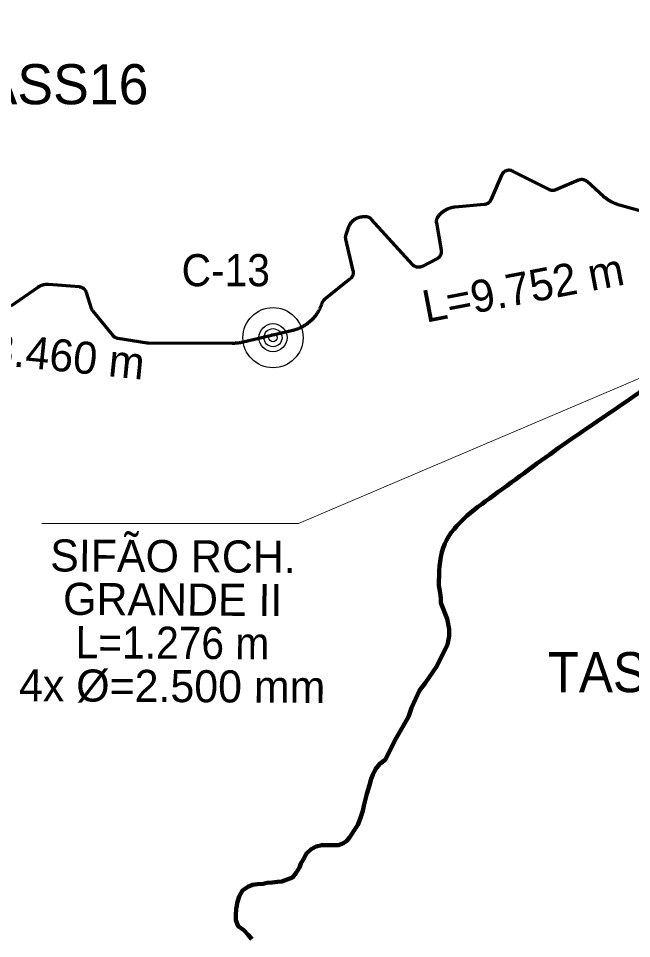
# Model space of a CAD drawing. Extents: x -1643653 to 4543381, y 1624270 to 13878484.
# Drawn here: x 659966 to 667613, y 8945036 to 8956510 of the extents above; entities that cross this region are included whole.
import ezdxf
from ezdxf.enums import TextEntityAlignment as Align

# ---------------------------------------------------------------- set-up
doc = ezdxf.new("R2010")
doc.units = 0
doc.header["$LTSCALE"] = 160
for name, color, linetype, lineweight in [('15', 7, 'Continuous', 25), ('24', 7, 'Continuous', 25), ('50', 7, 'Continuous', 13), ('53', 7, 'Continuous', 106), ('54', 7, 'Continuous', 25), ('60', 7, 'Continuous', 13), ('61', 7, 'Continuous', 70)]:
    doc.layers.add(name, color=color, linetype=linetype, lineweight=lineweight)

msp = doc.modelspace()

# ---------------------------------------------------------------- linework, layer by layer
at = {"layer": '15'}
for radius in [375, 175, 112.5, 50]:
    msp.add_circle((663140.8, 8952529.1), radius, dxfattribs=at)
at = {"layer": '24'}
for points in [[(664829.8, 8947803.3), (664867.6, 8947912.5), (664966.8, 8948127.8), (665039.6, 8948220.2), (665182.5, 8948431.5), (665314.9, 8948703.3), (665339.6, 8948809.3), (665338, 8948895), (665313.2, 8949024), (665234.2, 8949220.9), (665232.7, 8949279.6), (665225, 8949346.5), (665209.5, 8949437.1)], [(663068.8, 8945730.6), (663131.3, 8945735.3), (663198.9, 8945742.4), (663249, 8945749.7), (663384.3, 8945799), (663429.7, 8945856.3), (663470, 8945921.2), (663487.7, 8945971.1), (663523, 8946026), (663558.4, 8946098.4), (663618.7, 8946153.1), (663678.9, 8946185.3), (663749, 8946202.5), (663959.2, 8946201.4), (664019.3, 8946225.1), (664060.5, 8946254.5), (664092.8, 8946295.7), (664128.1, 8946345.7), (664157.6, 8946392.7), (664200.5, 8946455.3), (664234, 8946542.6), (664260.5, 8946630.8), (664274.2, 8946692.6), (664292, 8946760.1), (664309.9, 8946842.6), (664327.7, 8946897.5), (664345.4, 8946947.4), (664365.8, 8947027.4), (664386, 8947077.3), (664418.9, 8947147.2), (664471.8, 8947217), (664539.5, 8947266.7), (664677.1, 8947534.4), (664829.8, 8947803.3)], [(662877.9, 8945028.6), (662833.1, 8945083.8), (662775.8, 8945141.7), (662706, 8945192.1), (662678.8, 8945264.8), (662679.1, 8945327.3), (662682, 8945407.3), (662699.9, 8945494.8), (662720.2, 8945562.3), (662760.6, 8945637.1), (662825.9, 8945681.8), (662883.5, 8945706.5), (662948.6, 8945716.2), (663016.2, 8945720.9), (663068.8, 8945730.6)]]:
    msp.add_lwpolyline(points, dxfattribs=at)
msp.add_spline([(665209.5, 8949437.1), (665261.8, 8949907.3), (665888.8, 8950560.5), (666750.9, 8951187.5), (667665.3, 8951814.5), (668344.5, 8952363.1), (668788.7, 8952911.7), (669180.6, 8953564.9), (669154.4, 8954270.2), (669755.3, 8954662.1), (670486.8, 8955027.9), (671218.3, 8955785.5), (671166.1, 8956360.3), (671531.8, 8956726), (671479.6, 8956987.3), (670957.1, 8957405.3), (670695.8, 8957849.4), (671139.9, 8958502.5), (671845.3, 8959207.9), (672394, 8958789.9), (673047.1, 8959234), (673465.1, 8959834.9), (673177.7, 8960461.9), (673987.6, 8960749.3), (675163.2, 8960879.9), (676103.7, 8960906.1), (677253.2, 8961428.6), (677697.4, 8961559.2), (678115.4, 8962133.9), (678611.8, 8962369.1), (678820.8, 8962919.9), (679291, 8963704.1), (679918, 8964226.8), (679944.1, 8964697.3), (679709, 8965272.3), (679291, 8966004.2), (678115.4, 8966945.2)], degree=3, dxfattribs=at)
at = {"layer": '50'}
msp.add_lwpolyline([(668661.6, 8952425.6), (663458.1, 8950213.5), (660257, 8950213.5)], dxfattribs=at)
at = {"layer": '53'}
for points in [[(664829.8, 8947803.3), (664867.6, 8947912.5), (664966.8, 8948127.8), (665039.6, 8948220.2), (665182.5, 8948431.5), (665314.9, 8948703.3), (665339.6, 8948809.3), (665338, 8948895), (665313.2, 8949024), (665234.2, 8949220.9), (665232.7, 8949279.6), (665225, 8949346.5), (665209.5, 8949437.1)], [(663068.8, 8945730.6), (663131.3, 8945735.3), (663198.9, 8945742.4), (663249, 8945749.7), (663384.3, 8945799), (663429.7, 8945856.3), (663470, 8945921.2), (663487.7, 8945971.1), (663523, 8946026), (663558.4, 8946098.4), (663618.7, 8946153.1), (663678.9, 8946185.3), (663749, 8946202.5), (663959.2, 8946201.4), (664019.3, 8946225.1), (664060.5, 8946254.5), (664092.8, 8946295.7), (664128.1, 8946345.7), (664157.6, 8946392.7), (664200.5, 8946455.3), (664234, 8946542.6), (664260.5, 8946630.8), (664274.2, 8946692.6), (664292, 8946760.1), (664309.9, 8946842.6), (664327.7, 8946897.5), (664345.4, 8946947.4), (664365.8, 8947027.4), (664386, 8947077.3), (664418.9, 8947147.2), (664471.8, 8947217), (664539.5, 8947266.7), (664677.1, 8947534.4), (664829.8, 8947803.3)], [(662877.9, 8945028.6), (662833.1, 8945083.8), (662775.8, 8945141.7), (662706, 8945192.1), (662678.8, 8945264.8), (662679.1, 8945327.3), (662682, 8945407.3), (662699.9, 8945494.8), (662720.2, 8945562.3), (662760.6, 8945637.1), (662825.9, 8945681.8), (662883.5, 8945706.5), (662948.6, 8945716.2), (663016.2, 8945720.9), (663068.8, 8945730.6)]]:
    msp.add_lwpolyline(points, dxfattribs=at)
msp.add_spline([(665209.5, 8949437.1), (665261.8, 8949907.3), (665888.8, 8950560.5), (666750.9, 8951187.5), (667665.3, 8951814.5), (668344.5, 8952363.1), (668788.7, 8952911.7), (669180.6, 8953564.9), (669154.4, 8954270.2), (669755.3, 8954662.1), (670000.9, 8954785.2)], degree=3, dxfattribs=at)
at = {"layer": '60', "lineweight": 25}
msp.add_spline([(814781, 9009175.5), (814787.2, 9009173.4), (814796.9, 9009173.4), (814799.4, 9009172.4), (814805.1, 9009174.5), (814805.6, 9009176.5), (814811.7, 9009179.5), (814811.7, 9009179.5), (814801.5, 9009181), (814790.7, 9009181.5), (814784.1, 9009183.1), (814777.4, 9009185.1), (814778.4, 9009175.5)], degree=3, dxfattribs=at)
at = {"layer": '61'}
for points in [[(666049.2, 8954609.8), (666046.5, 8954608.8), (666043.9, 8954607.7), (666041.3, 8954606.6), (666038.8, 8954605.3), (666036.3, 8954604), (666033.8, 8954602.7), (666031.4, 8954601.2), (666029, 8954599.7), (666026.6, 8954598.1), (666024.3, 8954596.5), (666022.1, 8954594.8), (666019.9, 8954593), (666017.7, 8954591.2), (666015.6, 8954589.3), (666013.6, 8954587.3), (666011.6, 8954585.3), (666009.6, 8954583.3), (666007.8, 8954581.2), (666005.9, 8954579), (666004.2, 8954576.8), (666002.5, 8954574.5), (666000.9, 8954572.2), (665999.3, 8954569.8), (665997.8, 8954567.4), (665996.4, 8954565), (665995.1, 8954562.5), (665993.8, 8954560), (665992.6, 8954557.4), (665991.9, 8954556), (665857.4, 8954248), (665856.2, 8954245.4), (665855, 8954242.8), (665853.6, 8954240.3), (665852.3, 8954237.9), (665850.8, 8954235.4), (665849.3, 8954233), (665847.7, 8954230.7), (665846.1, 8954228.4), (665844.3, 8954226.2), (665842.6, 8954224), (665840.7, 8954221.8), (665838.8, 8954219.7), (665836.8, 8954217.7), (665834.8, 8954215.7), (665832.8, 8954213.8), (665830.6, 8954211.9), (665828.5, 8954210.1), (665826.2, 8954208.4), (665824, 8954206.7), (665821.6, 8954205.1), (665819.3, 8954203.5), (665816.8, 8954202), (665814.4, 8954200.6), (665811.9, 8954199.3), (665809.4, 8954198), (665806.8, 8954196.8), (665804.2, 8954195.7), (665801.6, 8954194.6), (665799, 8954193.7), (665796.3, 8954192.8), (665793.6, 8954191.9), (665790.8, 8954191.2), (665788.1, 8954190.5), (665785.3, 8954189.9), (665782.5, 8954189.4), (665779.8, 8954189), (665776.9, 8954188.6), (665774.5, 8954188.4), (665411.1, 8954156.3), (665406.2, 8954155.8), (665401.3, 8954155.2), (665396.5, 8954154.6), (665391.6, 8954153.9), (665386.8, 8954153.1), (665382, 8954152.2), (665377.1, 8954151.3), (665372.3, 8954150.3), (665367.6, 8954149.2), (665362.8, 8954148), (665358.1, 8954146.7), (665353.4, 8954145.4), (665348.7, 8954144), (665344, 8954142.5), (665339.4, 8954140.9), (665334.8, 8954139.3), (665330.2, 8954137.6), (665325.6, 8954135.8), (665321.1, 8954133.9), (665316.6, 8954132), (665312.1, 8954130), (665307.7, 8954127.9), (665303.3, 8954125.8), (665298.9, 8954123.5), (665294.6, 8954121.2), (665290.3, 8954118.9), (665286, 8954116.4), (665281.8, 8954113.9), (665277.7, 8954111.3), (665273.5, 8954108.7), (665269.5, 8954106)], [(667052.4, 8954478.2), (667050.2, 8954479.9), (667047.9, 8954481.6), (667045.6, 8954483.2), (667043.2, 8954484.7), (667040.8, 8954486.2), (667038.3, 8954487.6), (667035.8, 8954488.9), (667033.3, 8954490.2), (667030.7, 8954491.3), (667028.1, 8954492.5), (667025.5, 8954493.5), (667022.8, 8954494.5), (667020.1, 8954495.3), (667017.4, 8954496.1), (667014.7, 8954496.9), (667011.9, 8954497.5), (667009.2, 8954498.1), (667006.4, 8954498.6), (667003.6, 8954499), (667000.8, 8954499.3), (666997.9, 8954499.6), (666995.1, 8954499.8), (666992.3, 8954499.9), (666989.5, 8954499.9), (666986.6, 8954499.8), (666983.8, 8954499.7), (666981, 8954499.5), (666978.2, 8954499.2), (666975.4, 8954498.8), (666972.6, 8954498.3), (666969.8, 8954497.8), (666967.1, 8954497.2), (666964.3, 8954496.5), (666961.6, 8954495.7), (666958.9, 8954494.9), (666956.2, 8954493.9), (666953.6, 8954492.9), (666951.3, 8954492), (666667.3, 8954372), (666664.7, 8954371), (666662.1, 8954370), (666659.4, 8954369.1), (666656.7, 8954368.2), (666654, 8954367.5), (666651.2, 8954366.8), (666648.5, 8954366.2), (666645.7, 8954365.7), (666642.9, 8954365.2), (666640.1, 8954364.8), (666637.3, 8954364.5), (666634.5, 8954364.3), (666631.6, 8954364.2), (666628.8, 8954364.2), (666626, 8954364.2), (666623.1, 8954364.3), (666620.3, 8954364.5), (666617.5, 8954364.8), (666614.7, 8954365.1), (666611.9, 8954365.5), (666609.1, 8954366), (666606.3, 8954366.6), (666603.6, 8954367.3), (666600.9, 8954368), (666598.2, 8954368.8), (666595.5, 8954369.7), (666592.8, 8954370.7), (666590.2, 8954371.7), (666587.6, 8954372.9), (666585, 8954374.1), (666583.2, 8954374.9), (666128.8, 8954605.2), (666126.2, 8954606.4), (666123.7, 8954607.6), (666121, 8954608.7), (666118.4, 8954609.7), (666115.7, 8954610.6), (666113.1, 8954611.5), (666110.3, 8954612.3), (666107.6, 8954613), (666104.8, 8954613.7), (666102.1, 8954614.2), (666099.3, 8954614.7), (666096.5, 8954615.1), (666093.7, 8954615.4), (666090.9, 8954615.7), (666088, 8954615.8), (666085.2, 8954615.9), (666082.4, 8954615.9), (666079.6, 8954615.9), (666076.7, 8954615.7), (666073.9, 8954615.5), (666071.1, 8954615.2), (666068.3, 8954614.8), (666065.5, 8954614.3), (666062.7, 8954613.7), (666060, 8954613.1), (666057.2, 8954612.4), (666054.5, 8954611.6), (666051.8, 8954610.8), (666049.2, 8954609.8)], [(667956.4, 8954043.5), (667460.8, 8954182.6), (667454.7, 8954184.3), (667448.7, 8954186.1), (667442.6, 8954188), (667436.6, 8954190), (667430.6, 8954192.1), (667424.7, 8954194.2), (667418.7, 8954196.4), (667412.8, 8954198.7), (667407, 8954201), (667401.1, 8954203.5), (667395.3, 8954206), (667389.5, 8954208.5), (667383.8, 8954211.2), (667378.1, 8954213.9), (667372.4, 8954216.7), (667366.8, 8954219.6), (667361.2, 8954222.5), (667355.6, 8954225.5), (667350.1, 8954228.6), (667344.6, 8954231.7), (667339.1, 8954234.9), (667333.7, 8954238.2), (667328.4, 8954241.5), (667323.1, 8954245), (667317.8, 8954248.4), (667312.5, 8954252), (667307.3, 8954255.6), (667302.2, 8954259.3), (667297.1, 8954263), (667292.1, 8954266.8), (667287.1, 8954270.7), (667282.1, 8954274.7), (667277.2, 8954278.7), (667272.4, 8954282.7), (667267.6, 8954286.8), (667263.3, 8954290.6), (667056.8, 8954474.6), (667054.6, 8954476.4), (667052.4, 8954478.2)], [(664995.8, 8953415.5), (664993.2, 8953414.3), (664990.6, 8953413.3), (664987.9, 8953412.3), (664985.2, 8953411.5), (664982.5, 8953410.7), (664979.8, 8953409.9), (664977, 8953409.3), (664974.2, 8953408.7), (664971.5, 8953408.2), (664968.7, 8953407.8), (664965.8, 8953407.4), (664963, 8953407.2), (664960.2, 8953407), (664957.4, 8953406.9), (664954.6, 8953406.8), (664951.7, 8953406.9), (664948.9, 8953407), (664946.1, 8953407.3), (664943.3, 8953407.6), (664940.5, 8953407.9), (664937.7, 8953408.4), (664934.9, 8953408.9), (664932.1, 8953409.5), (664929.4, 8953410.2), (664926.7, 8953411), (664924, 8953411.8), (664921.3, 8953412.8), (664918.7, 8953413.8), (664916, 8953414.8), (664913.5, 8953416), (664910.9, 8953417.2), (664908.4, 8953418.5), (664905.9, 8953419.8), (664903.5, 8953421.3), (664901.1, 8953422.8), (664898.7, 8953424.3), (664896.4, 8953426), (664894.1, 8953427.7), (664891.9, 8953429.4), (664889.7, 8953431.2), (664887.6, 8953433.1), (664885.6, 8953435.1), (664883.6, 8953437), (664881.6, 8953439.1), (664881.1, 8953439.7), (664369.6, 8954003.5), (664367.6, 8954005.5), (664365.7, 8954007.5), (664363.6, 8954009.5), (664361.5, 8954011.4), (664359.4, 8954013.2), (664357.2, 8954015), (664354.9, 8954016.7), (664352.6, 8954018.4), (664350.3, 8954019.9), (664347.9, 8954021.5), (664345.5, 8954022.9), (664343, 8954024.3), (664340.5, 8954025.6), (664337.9, 8954026.8), (664335.3, 8954028), (664332.7, 8954029.1), (664330.1, 8954030.1), (664327.4, 8954031), (664324.7, 8954031.9), (664322, 8954032.7), (664319.3, 8954033.4), (664316.5, 8954034), (664313.8, 8954034.6), (664311, 8954035.1), (664308.2, 8954035.5), (664305.3, 8954035.8), (664302.5, 8954036), (664299.7, 8954036.2), (664296.9, 8954036.2), (664294.1, 8954036.2), (664291.2, 8954036.2), (664290.1, 8954036.1), (664256.9, 8954034.3), (664256.9, 8954034.3), (664252.9, 8954034.1), (664248.9, 8954033.7), (664245, 8954033.3), (664241, 8954032.8), (664237, 8954032.2), (664233.1, 8954031.6), (664229.1, 8954030.9), (664225.2, 8954030.1), (664221.3, 8954029.2), (664217.4, 8954028.2), (664213.6, 8954027.2), (664209.7, 8954026), (664205.9, 8954024.8), (664202.1, 8954023.6), (664198.4, 8954022.2), (664194.6, 8954020.8), (664190.9, 8954019.3), (664187.2, 8954017.7), (664183.6, 8954016.1), (664180, 8954014.4)], [(665269.5, 8954106), (665265.4, 8954103.2), (665261.4, 8954100.4), (665257.5, 8954097.5), (665253.6, 8954094.5), (665249.8, 8954091.5), (665246, 8954088.4), (665242.2, 8954085.2), (665238.5, 8954082), (665234.9, 8954078.7), (665231.3, 8954075.4), (665227.8, 8954072), (665224.3, 8954068.5), (665220.9, 8954065), (665217.5, 8954061.5), (665214.2, 8954057.8), (665211, 8954054.2), (665207.8, 8954050.4), (665204.7, 8954046.7), (665204.2, 8954046.1), (665198.6, 8954039.2), (665196.9, 8954037), (665195.2, 8954034.7), (665193.6, 8954032.4), (665192, 8954030), (665190.5, 8954027.6), (665189.1, 8954025.2), (665187.8, 8954022.7), (665186.5, 8954020.2), (665185.3, 8954017.6), (665184.2, 8954015), (665183.1, 8954012.4), (665182.1, 8954009.7), (665181.2, 8954007.1), (665180.4, 8954004.3), (665179.6, 8954001.6), (665179, 8953998.9), (665178.3, 8953996.1), (665177.8, 8953993.3), (665177.4, 8953990.5), (665177, 8953987.7), (665176.7, 8953984.9), (665176.5, 8953982.1), (665176.4, 8953979.3), (665176.4, 8953976.5), (665176.4, 8953973.6), (665176.5, 8953970.8), (665176.7, 8953968), (665177, 8953965.2), (665177.3, 8953962.3), (665177.8, 8953959.6), (665177.9, 8953959.1), (665237.4, 8953618.5), (665237.9, 8953615.7), (665238.2, 8953612.9), (665238.5, 8953610.1), (665238.8, 8953607.3), (665238.9, 8953604.4), (665238.9, 8953601.6), (665238.9, 8953598.8), (665238.8, 8953596), (665238.6, 8953593.1), (665238.3, 8953590.3), (665238, 8953587.5), (665237.6, 8953584.7), (665237, 8953581.9), (665236.5, 8953579.2), (665235.8, 8953576.4), (665235.1, 8953573.7), (665234.2, 8953571), (665233.3, 8953568.3), (665232.4, 8953565.6), (665231.3, 8953563), (665230.2, 8953560.4), (665229, 8953557.8), (665227.8, 8953555.3), (665226.4, 8953552.8), (665225, 8953550.4), (665223.5, 8953548), (665222, 8953545.6), (665220.4, 8953543.3), (665218.7, 8953541), (665217, 8953538.8), (665215.2, 8953536.6), (665213.3, 8953534.4), (665211.4, 8953532.4), (665209.4, 8953530.3), (665207.4, 8953528.4), (665205.3, 8953526.5), (665203.2, 8953524.6), (665201, 8953522.8), (665198.7, 8953521.1), (665196.4, 8953519.5), (665194.1, 8953517.9), (665191.7, 8953516.3), (665189.3, 8953514.9), (665186.8, 8953513.5), (665184.6, 8953512.3), (665000.9, 8953417.9), (664998.3, 8953416.7), (664995.8, 8953415.5)], [(664180, 8954014.4), (664176.4, 8954012.6), (664172.9, 8954010.7), (664169.4, 8954008.8), (664165.9, 8954006.8), (664162.5, 8954004.7), (664159.1, 8954002.6), (664155.8, 8954000.4), (664152.5, 8953998.1), (664149.2, 8953995.8), (664146, 8953993.4), (664142.9, 8953990.9), (664139.8, 8953988.4), (664136.7, 8953985.8), (664133.7, 8953983.1), (664130.8, 8953980.4), (664127.9, 8953977.7), (664125.1, 8953974.8), (664122.3, 8953972), (664119.6, 8953969), (664116.9, 8953966), (664114.3, 8953963), (664111.8, 8953959.9), (664109.3, 8953956.8), (664106.9, 8953953.6), (664104.5, 8953950.3), (664102.3, 8953947), (664100, 8953943.7), (664097.9, 8953940.3), (664095.8, 8953936.9), (664093.8, 8953933.5), (664091.9, 8953930), (664090, 8953926.4), (664088.2, 8953922.8), (664086.5, 8953919.2), (664084.8, 8953915.6), (664083.2, 8953911.9), (664081.7, 8953908.2), (664080.3, 8953904.5), (664078.9, 8953900.7), (664078.8, 8953900.5), (664048.3, 8953812.9), (664047.4, 8953810.2), (664046.6, 8953807.5), (664045.8, 8953804.8), (664045.2, 8953802), (664044.6, 8953799.2), (664044.1, 8953796.5), (664043.6, 8953793.7), (664043.3, 8953790.9), (664043, 8953788), (664042.8, 8953785.2), (664042.7, 8953782.4), (664042.7, 8953779.6), (664042.7, 8953776.7), (664042.9, 8953773.9), (664043.1, 8953771.1), (664043.4, 8953768.3), (664043.7, 8953765.5), (664044.2, 8953762.7), (664044.7, 8953759.9), (664045.3, 8953757.1), (664045.4, 8953756.9), (664138.3, 8953363.8), (664139, 8953361.1), (664139.5, 8953358.3), (664139.9, 8953355.5), (664140.3, 8953352.7), (664140.6, 8953349.9), (664140.8, 8953347.1), (664141, 8953344.3), (664141, 8953341.4), (664141, 8953338.6), (664140.9, 8953335.8), (664140.7, 8953333), (664140.5, 8953330.1), (664140.1, 8953327.3), (664139.7, 8953324.5), (664139.2, 8953321.8), (664138.6, 8953319), (664138, 8953316.2), (664137.2, 8953313.5), (664136.4, 8953310.8), (664135.5, 8953308.1), (664134.6, 8953305.4), (664133.5, 8953302.8), (664132.4, 8953300.2), (664131.2, 8953297.6), (664130, 8953295.1), (664128.6, 8953292.6), (664127.2, 8953290.2), (664125.8, 8953287.7), (664124.2, 8953285.4), (664122.6, 8953283), (664121, 8953280.8), (664119.2, 8953278.5), (664117.4, 8953276.3), (664115.6, 8953274.2), (664113.7, 8953272.1), (664111.7, 8953270.1), (664109.7, 8953268.1)], [(664109.7, 8953268.1), (664107.6, 8953266.2), (664105.4, 8953264.3), (664103.8, 8953263), (663782, 8953003.8), (663779.8, 8953002), (663777.7, 8953000.1), (663775.6, 8952998.2), (663773.6, 8952996.2), (663771.6, 8952994.2), (663769.7, 8952992.1), (663767.9, 8952989.9), (663766.1, 8952987.7), (663764.4, 8952985.5), (663762.7, 8952983.2), (663761.1, 8952980.8), (663759.6, 8952978.5), (663758.2, 8952976), (663756.8, 8952973.6), (663755.5, 8952971.1), (663754.2, 8952968.5), (663753.1, 8952965.9), (663752, 8952963.3), (663750.9, 8952960.7), (663750.3, 8952958.8), (663744.3, 8952941.8), (663742.2, 8952935.8), (663740, 8952929.9), (663737.7, 8952924), (663735.4, 8952918.1), (663733, 8952912.2), (663730.5, 8952906.4), (663727.9, 8952900.7), (663725.2, 8952894.9), (663722.5, 8952889.2), (663719.8, 8952883.5), (663716.9, 8952877.9), (663714, 8952872.3), (663711, 8952866.7), (663707.9, 8952861.2), (663704.8, 8952855.7), (663701.6, 8952850.2), (663698.3, 8952844.8), (663694.9, 8952839.4), (663691.5, 8952834.1), (663688.1, 8952828.8), (663684.5, 8952823.6), (663680.9, 8952818.4), (663677.2, 8952813.3), (663673.5, 8952808.2), (663669.7, 8952803.1), (663665.8, 8952798.1), (663661.9, 8952793.2), (663657.9, 8952788.2), (663653.8, 8952783.4), (663649.7, 8952778.6), (663645.5, 8952773.8), (663641.3, 8952769.2), (663637, 8952764.5), (663632.6, 8952759.9), (663628.2, 8952755.4), (663623.8, 8952750.9), (663619.2, 8952746.5), (663614.7, 8952742.1), (663610, 8952737.8), (663605.3, 8952733.6), (663600.6, 8952729.4), (663595.8, 8952725.3), (663590.9, 8952721.2), (663586, 8952717.2), (663581.1, 8952713.3), (663576.1, 8952709.4), (663571.1, 8952705.6), (663566, 8952701.8), (663560.8, 8952698.2), (663555.6, 8952694.6), (663550.4, 8952691), (663545.1, 8952687.5), (663539.8, 8952684.1), (663534.4, 8952680.7), (663529, 8952677.5), (663523.6, 8952674.2), (663518.1, 8952671.1), (663512.6, 8952668), (663507, 8952665), (663501.4, 8952662.1), (663495.8, 8952659.2), (663490.1, 8952656.4), (663484.4, 8952653.7), (663478.6, 8952651.1), (663472.8, 8952648.5), (663467, 8952646), (663461.2, 8952643.6), (663455.3, 8952641.2), (663449.4, 8952638.9), (663443.5, 8952636.7), (663437.5, 8952634.6), (663431.6, 8952632.6), (663425.6, 8952630.6), (663419.5, 8952628.7), (663413.5, 8952626.8)], [(660771.8, 8953146.4), (660769.4, 8953147.9), (660767, 8953149.3), (660764.5, 8953150.6), (660761.9, 8953151.8), (660759.3, 8953153), (660756.8, 8953154.1), (660754.1, 8953155.1), (660751.5, 8953156.1), (660748.8, 8953157), (660746.1, 8953157.8), (660743.3, 8953158.5), (660740.6, 8953159.1), (660737.8, 8953159.7), (660735, 8953160.2), (660732.2, 8953160.6), (660729.4, 8953160.9), (660726.9, 8953161.2), (660339.2, 8953191.6), (660335.2, 8953191.9), (660331.2, 8953192.1), (660327.2, 8953192.2), (660323.2, 8953192.2), (660319.2, 8953192.2), (660315.2, 8953192), (660311.2, 8953191.8), (660307.2, 8953191.5), (660303.2, 8953191.2), (660299.3, 8953190.7), (660295.3, 8953190.2), (660291.4, 8953189.6), (660287.4, 8953188.9), (660283.5, 8953188.2), (660279.6, 8953187.3), (660275.7, 8953186.4), (660271.8, 8953185.4), (660268, 8953184.3), (660264.1, 8953183.2), (660260.3, 8953181.9), (660256.5, 8953180.6), (660252.8, 8953179.3), (660249.1, 8953177.8), (660245.4, 8953176.3), (660241.7, 8953174.7), (660238.1, 8953173), (660234.5, 8953171.3), (660230.9, 8953169.5), (660227.4, 8953167.6), (660223.9, 8953165.6), (660220.4, 8953163.6), (660217, 8953161.5), (660213.7, 8953159.3), (660210.3, 8953157.1), (660208.9, 8953156.1), (659872.4, 8952920.6)], [(663413.5, 8952626.8), (663407.4, 8952625.1), (663401.3, 8952623.4), (663395.2, 8952621.8), (663389, 8952620.3), (663386.4, 8952619.7), (662751.9, 8952470.8), (662745.7, 8952469.4), (662739.5, 8952468.1), (662733.3, 8952466.8), (662727.1, 8952465.7), (662720.9, 8952464.6), (662714.7, 8952463.5), (662708.4, 8952462.6), (662702.1, 8952461.8), (662695.8, 8952461), (662689.6, 8952460.3), (662683.3, 8952459.7), (662677, 8952459.1), (662670.7, 8952458.7), (662664.3, 8952458.3), (662658, 8952458), (662651.7, 8952457.8), (662645.4, 8952457.6), (662639.1, 8952457.6), (662636.4, 8952457.6), (661588, 8952460.2), (661585.2, 8952460.2), (661582.4, 8952460.4), (661579.6, 8952460.6), (661576.8, 8952460.9), (661574, 8952461.2), (661572.7, 8952461.4), (661207.8, 8952519), (661205, 8952519.5), (661202.3, 8952520), (661199.5, 8952520.6), (661196.8, 8952521.4), (661194.1, 8952522.2), (661191.4, 8952523), (661188.7, 8952524), (661186.1, 8952525), (661183.5, 8952526.1), (661180.9, 8952527.2), (661178.3, 8952528.5), (661175.8, 8952529.8), (661173.4, 8952531.2), (661170.9, 8952532.6), (661168.5, 8952534.1), (661166.2, 8952535.7), (661163.9, 8952537.4), (661161.7, 8952539.1), (661159.5, 8952540.9), (661157.3, 8952542.7), (661155.2, 8952544.6), (661153.2, 8952546.6), (661151.2, 8952548.6), (661149.2, 8952550.7), (661147.4, 8952552.8), (661146.2, 8952554.2), (660896.3, 8952857.8), (660894.5, 8952860.1), (660892.8, 8952862.3), (660891.2, 8952864.6), (660889.6, 8952867), (660888.1, 8952869.4), (660886.7, 8952871.8), (660885.3, 8952874.3), (660884, 8952876.8), (660882.8, 8952879.3), (660881.6, 8952881.9), (660880.5, 8952884.5), (660879.5, 8952887.2), (660878.6, 8952889.8), (660878.2, 8952891.1), (660814.4, 8953091.8), (660813.5, 8953094.5), (660812.5, 8953097.1), (660811.5, 8953099.7), (660810.4, 8953102.3), (660809.2, 8953104.9), (660807.9, 8953107.4), (660806.6, 8953109.9), (660805.2, 8953112.4), (660803.7, 8953114.8), (660802.1, 8953117.2), (660800.5, 8953119.5), (660798.9, 8953121.8), (660797.1, 8953124), (660795.3, 8953126.2), (660793.5, 8953128.3), (660791.5, 8953130.4), (660789.6, 8953132.4), (660787.5, 8953134.4), (660785.4, 8953136.3), (660783.3, 8953138.1), (660781.1, 8953139.9), (660778.9, 8953141.6), (660776.6, 8953143.3), (660774.2, 8953144.9), (660771.8, 8953146.4)]]:
    msp.add_lwpolyline(points, dxfattribs=at)

# ---------------------------------------------------------------- texts
at = {"layer": '15', "width": 0.95}
msp.add_text('C-13', height=400, dxfattribs=at).set_placement((662001.2, 8953170.9))
at = {"layer": '50'}
for s, rotation, p in [('L=9.752 m', 10.835, (665047.5, 8952715.5)), ('L=8.460 m', 354.202, (658989.9, 8952261.9))]:
    msp.add_text(s, height=400, rotation=rotation, dxfattribs=at).set_placement(p)
for s, p in [('SIFÃO RCH.', (661892.3, 8949605.3)), ('GRANDE II', (661889.1, 8949065.3)), ('4x Ø=2.500 mm', (661882.6, 8947985.4))]:
    msp.add_text(s, height=400, rotation=359.655, dxfattribs=at).set_placement(p, align=Align.CENTER)
at = {"layer": '50', "width": 0.95}
msp.add_text('L=1.276 m', height=400, rotation=359.655, dxfattribs=at).set_placement((661885.8, 8948525.3), align=Align.CENTER)
at = {"layer": '54'}
msp.add_text('TASS16', height=500, dxfattribs=at).set_placement((660342.6, 8955439.4), align=Align.CENTER)
at = {"layer": '54', "width": 0.95}
msp.add_text('TAST1', height=500, dxfattribs=at).set_placement((667556.3, 8948108.8), align=Align.CENTER)

doc.saveas('drawing.dxf')
